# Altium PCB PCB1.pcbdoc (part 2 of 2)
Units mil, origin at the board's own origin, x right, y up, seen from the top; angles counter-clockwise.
Board outline 9373 x 7411 mil, 2 copper layers (Top Layer, Bottom Layer); 228 components, 128 nets, 653 pads, 371 vias.
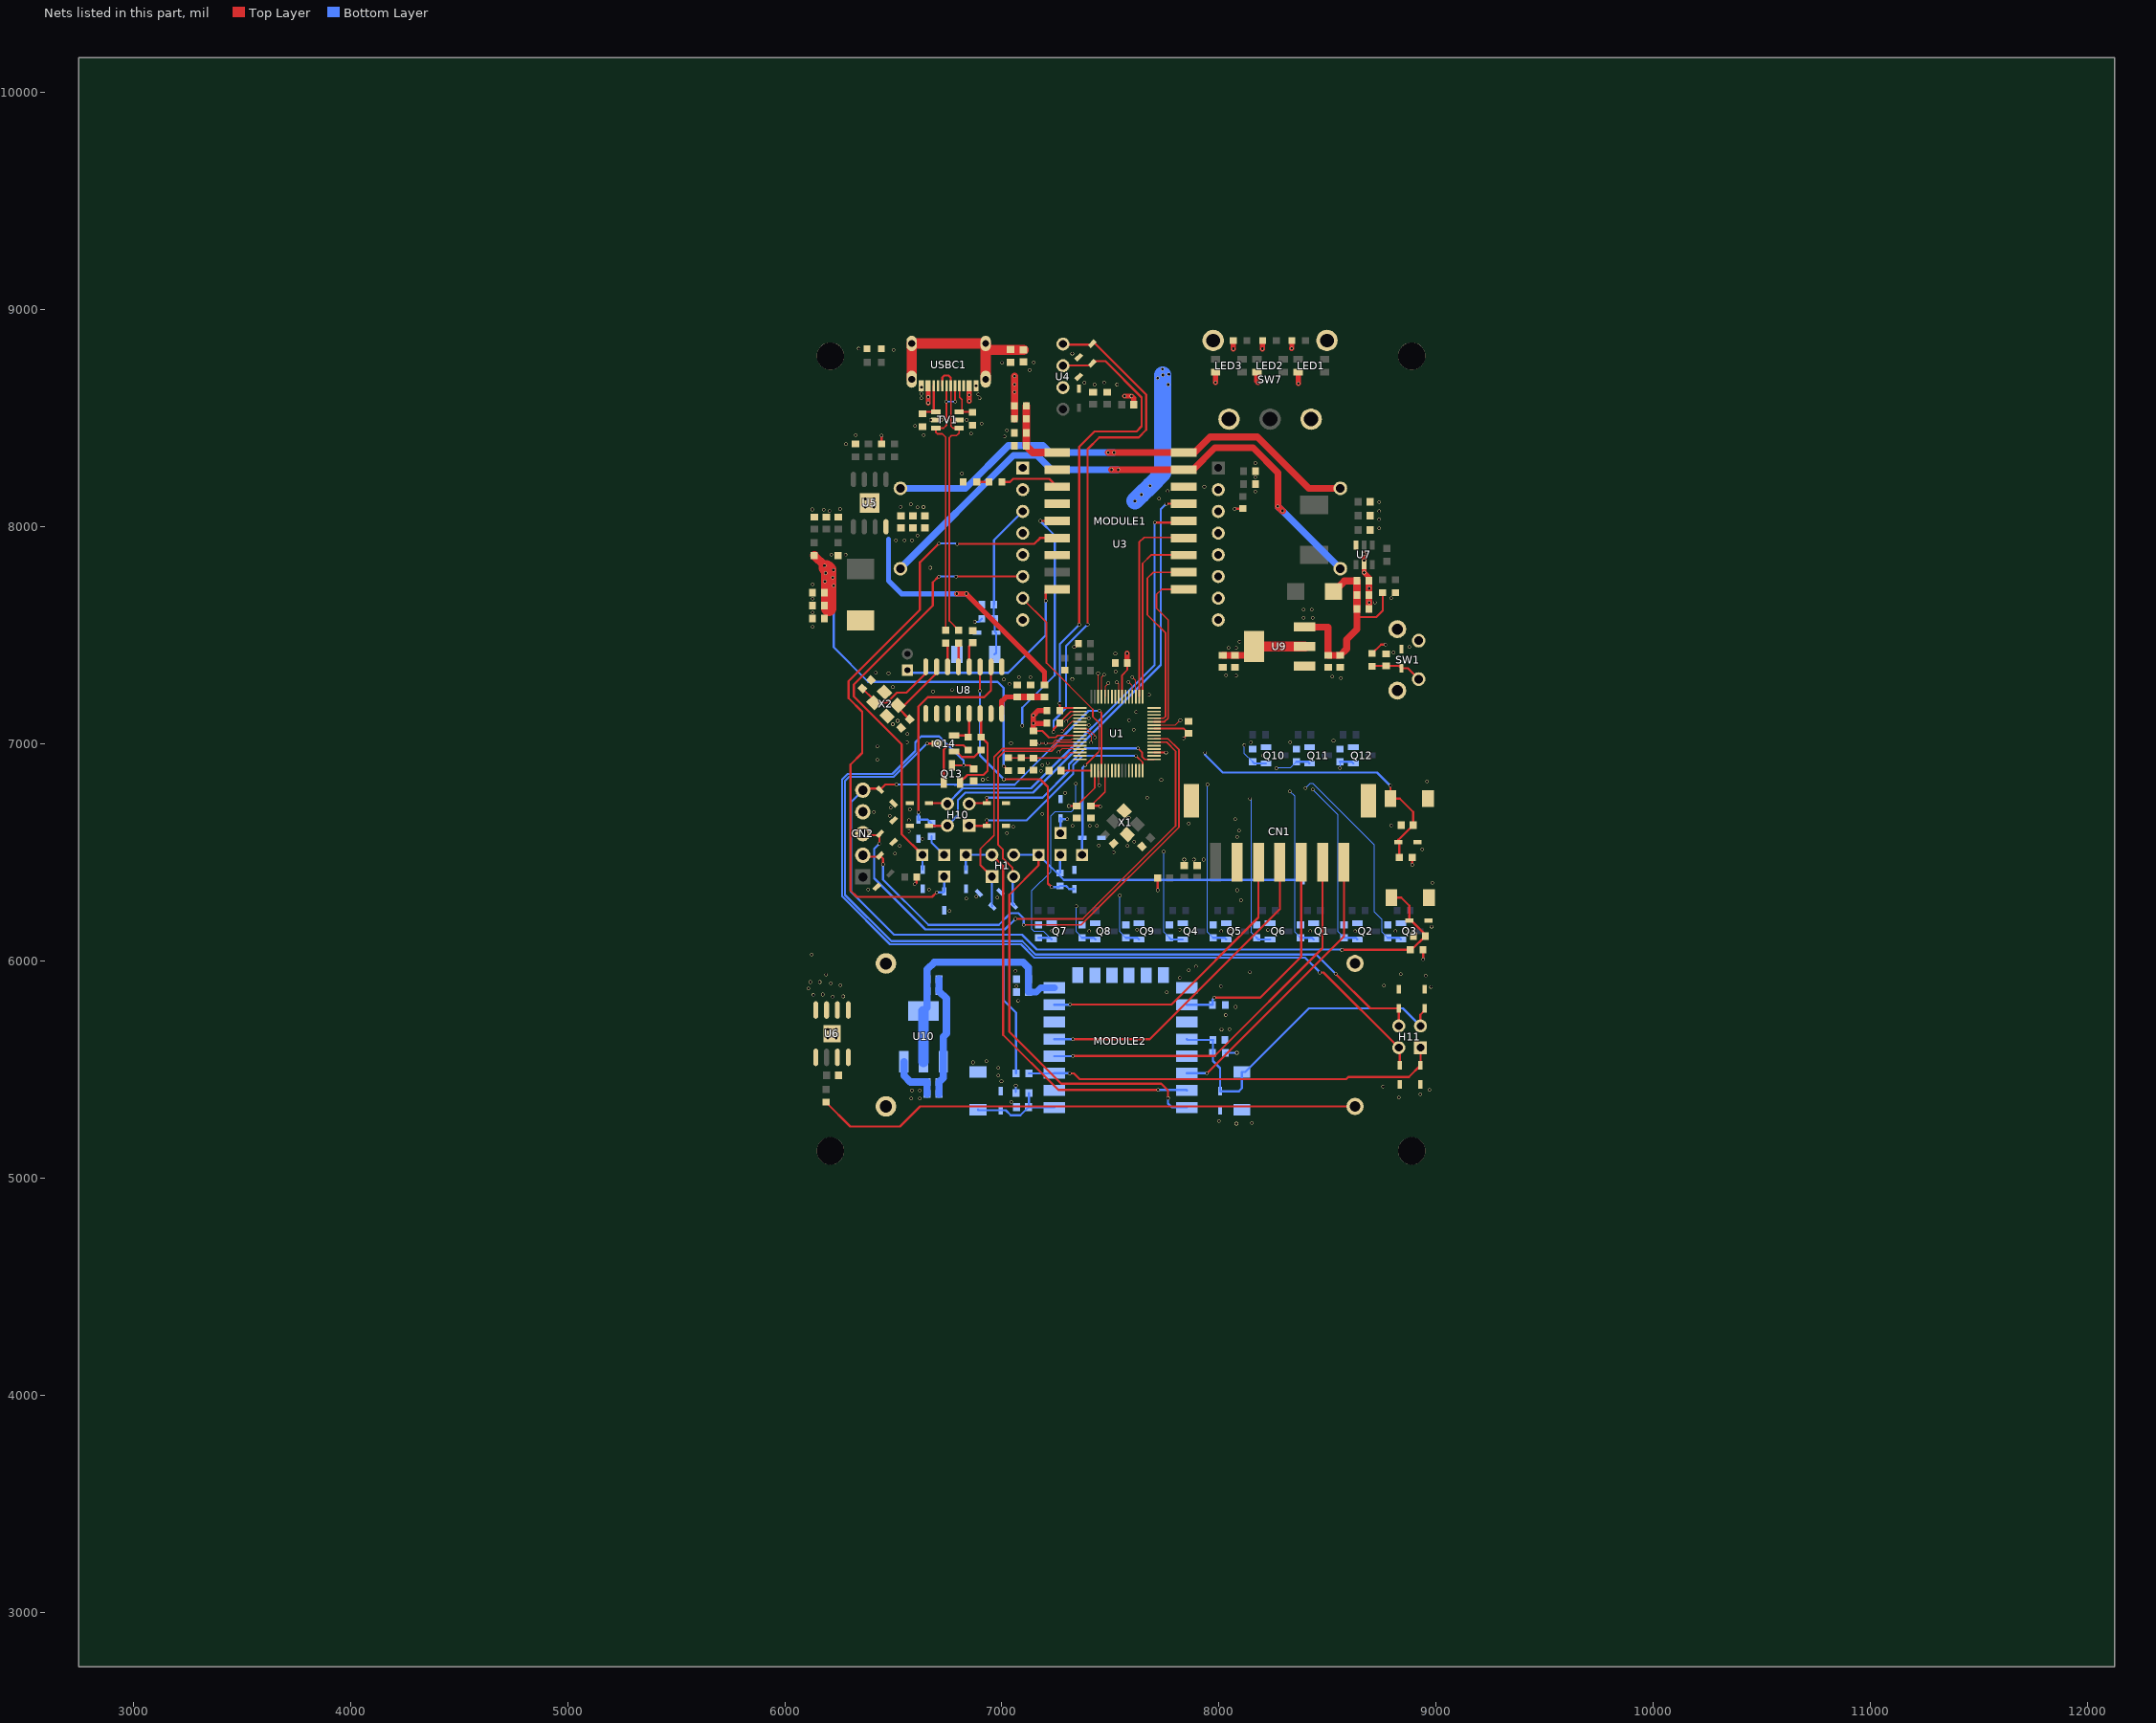
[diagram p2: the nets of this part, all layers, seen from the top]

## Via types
v1: diameter 15.75, hole 11.81, Top Layer to Bottom Layer, 371 vias

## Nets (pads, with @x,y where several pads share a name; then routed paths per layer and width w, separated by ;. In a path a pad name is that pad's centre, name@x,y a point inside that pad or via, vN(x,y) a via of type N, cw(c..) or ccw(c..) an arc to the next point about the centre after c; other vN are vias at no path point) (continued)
$5N266: MIC1.1 MODULE1.9 | length 973.1
  Top Layer w10: v1(7202,7660) 7202,7702.99 7212.04,7713.03 MODULE1.9@7255.04,7713.03
  Bottom Layer w10: MIC1.1@6565,7340.6 6577.6,7328 7029,7328 7202,7501 v1(7202,7660)
$5N267: MODULE1.3 R19.2 | length 276.3
  Top Layer w10: R19.2@6999.7,8208 7038,8208 7052,8222 7218.52,8222 MODULE1.3@7255.04,8185.48
$5N268: LED4.2 R19.1 | length 55.9
  Top Layer w10: LED4.2@6884.5,8207.8 6884.7,8208 R19.1@6940.3,8208
$5N526: C53.2 C54.2 L8.2 L9.2 MODULE1.1 | length 340.1
  Top Layer w34: L8.2@7113.18,8557.9 7112.56,8557.28 C54.2@7112.56,8433 C53.2@7112.56,8373 7142.59,8342.97 MODULE1.1@7255.04,8342.97
$6N1307: C55.1 C56.1 L10.1 U8.16 | length 261.9
  Top Layer w24: U8.16@6999.87,7140.61 6999.87,7198 7019.12,7217.26 C55.1@7071.46,7217.26
  Top Layer w32: C55.1@7071.46,7217.26 C56.1@7131.46,7217.26 L10.1@7196.46,7217.26
$6N1422: C57.1 U8.4 | length 118.1
  Top Layer w10: U8.4@6849.87,7356.02 6849.87,7450.66 C57.1@6866.46,7467.26
$6N1638: C59.1 U8.8 X2.3 | length 412.4
  Top Layer w10: C59.1@6358.11,7256.16 6410.64,7203.63 X2.3@6410.64,7190.86 6470.86,7190.86 6517,7237 6561,7237 6649.87,7325.87 U8.8@6649.87,7356.02
$6N1644: C58.2 U8.7 X2.1 | length 356.8
  Top Layer w10: C58.2@6575.11,7114.08 6520.61,7168.58 X2.1@6520.61,7178.33 6551.33,7178.33 6699.87,7326.87 U8.7@6699.87,7356.02
$6N1700: R60.2 U8.5 | length 109.8
  Top Layer w10: U8.5@6799.87,7356.02 6801.46,7357.61 R60.2@6801.46,7465.16
$6N1728: R61.2 U8.6 | length 112.6
  Top Layer w10: R61.2@6741.46,7465.16 6749.87,7456.75 U8.6@6749.87,7356.02
$6N1913: Q13.1 R62.1 | length 280.8
  Top Layer w10: Q13.1@6732.6,6823.6 6733,6824.03 6733,6975 6753,6995 6823.34,6995 R62.1@6845,6973.3
$6N1915: Q14.1 R63.1 | length 149.2
  Top Layer w10: Q14.1@6779.4,6965.6 6791.37,6965.6 6815.97,6941 6872.66,6941 R63.1@6905,6973.3
$7N380: H2.1 R64.2 | length 84.2
  Bottom Layer w10: R64.2@7268.48,6406.01 7268.48,6489.16 H2.1@7269.25,6489.93
$7N857: H6.1 R65.2 | length 110
  Bottom Layer w10: R65.2@6676.51,6574.97 6676.51,6545.97 6732.55,6489.93 H6.1@6734.25,6489.93
BAT_SENSE: C32.2 R44.2 R45.1 U1.14 | length 340.7
  Top Layer w7: R45.1@7030,6937.7 7031.7,6936 7288,6936 7313.39,6961.39 U1.14@7359.53,6961.39
BGND: BT1.2 BT2.2 C45.2 U6.5 U6.7 U6.8 U6.9
  other v1: 6198.14,5646.68 6237.51,5646.68 6198.14,5686.05 6237.51,5686.05
CAM_UART0_RX: D20.1 H8.1 U3.14 | length 2030.6
  Top Layer w10: H8.1@6634.25,6489.93 6539,6585.18 6539,6999 6318,7220 6318,7274 6682,7638 6682,7745 6709,7772 v1(6710,7772) ; v1(6789,7771.97) U3.14@7096.38,7771.97
  Bottom Layer w10: H8.1@6634.25,6489.93 6635,6489.18 D20.1@6635,6422 ; v1(6710,7772) v1(6789,7771.97)
CAM_UART0_TX: D19.1 H4.1 U3.15 | length 1360.1
  Top Layer w5: 7444,6963 7447,6966 7447,7098.21 7444,7101.21
  Top Layer w7.9: U3.15@7096.38,7671.97 7096.38,7668.73 7205.38,7559.73 7205.38,7373.5 7419,7159.88 7419,7126.21 7444,7101.21 ; v1(7384,6904) 7385,6904 7444,6963
  Bottom Layer w10: H4.1@7369.25,6489.93 7369.25,6566.25 D19.1@7371,6568 7371,6891 v1(7384,6904)
CC1: R58.2 TV1.3 USBC1.A5 | length 189.7
  Top Layer w6: USBC1.A5@6804.21,8650.59 6804.21,8597.79 6816,8586 6816,8534.25 TV1.3@6813.21,8531.46
  Top Layer w10: TV1.3@6804.21,8531.46 TV1.3@6803.15,8530.4 6862.26,8530.4 R58.2@6865,8527.7
CC2: R59.2 TV1.4 USBC1.B5 | length 190.1
  Top Layer w10: R59.2@6635,8521.7 6643.74,8530.4 TV1.4@6696.85,8530.4 6686.1,8541.15 USBC1.B5@6686.1,8650.59
CH340G_BOOT: D27.1 H11.4 Q14.3 | length 3866.8
  Top Layer w10: v1(6655,7003) Q14.3@6700.6,7003 ; v1(8537,5942) 8696.25,5782.75 D27.1@8827.59,5782.75 H11.4@8827.59,5701.75
  Bottom Layer w10: v1(6655,7003) 6501,6849 6296,6849 6278,6831 6278,6305 6491,6092 7094,6092 7155,6031 8448,6031 v1(8537,5942)
CH340G_DTR: Q14.2 R62.2 U8.13 | length 178.8
  Top Layer w10: Q14.2@6779.4,7040.4 6837.26,7040.4 R62.2@6845,7032.7 6849.87,7037.53 U8.13@6849.87,7140.61
CH340G_EN: C60.1 D26.1 H11.2 Q13.3 | length 4313.7
  Top Layer w10: Q13.3@6770,6902.4 v1(6824.17,6902.37) 6853.19,6902.37 C60.1@6870,6885.56 ; v1(8465,5948) 8481.34,5948 H11.2@8827.59,5601.75 8832.59,5596.75 D26.1@8832.59,5520.75
  Bottom Layer w10: v1(6824.17,6902.37) 6824.17,6923.83 6712,7036 6629,7036 6601,7008 6601,6968.82 6495.19,6863.02 6290.19,6863.02 6263.98,6836.81 6263.98,6299.19 6485.19,6077.98 7088.19,6077.98 7149.19,6016.98 8396.02,6016.98 v1(8465,5948)
CH340G_RTS: Q13.2 R63.2 U8.14 | length 426.5
  Top Layer w10: Q13.2@6807.4,6823.6 6841.77,6858 6915,6858 6934,6877 6934,7003.66 R63.2@6905,7032.7 6905,7135.48 U8.14@6899.87,7140.61
CH340G_RX: D15.1 R64.1 U8.3 | length 1363.1
  Top Layer w10: v1(6899,7245) 6899,7355.15 U8.3@6899.87,7356.02 ; v1(7009,6838) 7177,6838 7212,6803 7212,6358 v1(7229,6341)
  Bottom Layer w10: v1(6899,7245) 6899,6948 v1(7009,6838) ; v1(7229,6341) 7262.79,6341 R64.1@7268.48,6346.65 7295.08,6346.69 7309.38,6332.39 D15.1@7333.38,6332.39
CH340G_TX: D16.1 R65.1 U8.2 | length 1063.9
  Top Layer w10: v1(6616,6686) 6616,7173 6659,7216 6919,7216 6949.87,7246.87 U8.2@6949.87,7356.02
  Bottom Layer w10: v1(6616,6686) 6616,6653 D16.1@6615,6652 6658.8,6652 R65.1@6676.51,6634.33
D0_LCD_DC: CN1.2 MODULE2.4 | length 1837.3
  Top Layer w10: v1(7327,5564) 7980,5564 8476.84,6060.85 CN1.2@8476.84,6456.27
  Bottom Layer w10: MODULE2.4@7241.26,5562.69 7325.69,5562.69 v1(7327,5564)
D1_LCD_RST: CN1.1 MODULE2.20 | length 1326.8
  Top Layer w10: v1(7945,5484) 8575.27,6114.27 CN1.1@8575.27,6456.27
  Bottom Layer w10: MODULE2.20@7851.49,5483.94 v1@7944.94,5483.94
D5_LCD_SCK: CN1.4 MODULE2.5 | length 1503.3
  Top Layer w10: v1(7327,5641) 7681,5641 8280,6239.99 CN1.4@8280,6456.27
  Bottom Layer w10: MODULE2.5@7241.26,5641.43 7326.57,5641.43 v1(7327,5641)
D7_LCD_DIN: CN1.5 MODULE2.7 | length 1361.8
  Top Layer w10: v1(7314,5801) 7781,5801 8181.57,6201.57 CN1.5@8181.57,6456.27
  Bottom Layer w10: MODULE2.7@7241.26,5798.91 7311.91,5798.91 v1(7314,5801)
D8_LCD_CS: CN1.3 MODULE2.16 R32.2 | length 1070.7
  Top Layer w10: v1(7978,5833) 8190,5833 8378.42,6021.43 CN1.3@8378.42,6456.27
  Bottom Layer w10: MODULE2.16@7851.49,5798.9 7969.4,5798.9 R32.2@7970.3,5798 7970.3,5825.3 v1(7978,5833)
ESP32CAM_IO0_BOOT: C33.2 D9.1 R46.1 SW6.1 U3.11 | length 721.6
  Bottom Layer w10: SW6.1@6966.62,7413 6973.81,7420.19 D9.1@6973.81,7513 6967.4,7519.41 R46.1@6967.4,7578 6963.03,7582.36 C33.2@6963.03,7643 6964,7643.97 6964,7939.59 U3.11@7096.38,8071.97
ESP8266_EN: D25.1 H11.1 MODULE2.3 R31.1 | length 1921.9
  Top Layer w10: v1(7312,5483) 7332,5483 7358,5457 8585,5457 8595,5467 8873.84,5467 D25.1@8927.59,5520.75 H11.1@8927.59,5601.75
  Bottom Layer w10: R31.1@7124.7,5483 7240.31,5483 MODULE2.3@7241.26,5483.95 7311.05,5483.95 v1(7312,5483)
ESP8266_IO0_BOOT: C25.2 D7.1 D28.1 H11.3 MODULE2.18 R29.1 SW4.1 | length 1621.2
  Top Layer w10: H11.3@8927.59,5701.75 8926.59,5702.75 8926.59,5753.75 8947.59,5774.75 D28.1@8947.59,5782.75
  Bottom Layer w10: MODULE2.18@7851.49,5641.42 7854.92,5638 C25.2@7972.44,5638 7972,5637.56 7972,5541 8005,5508 D7.1@8005,5402 8006,5401 8091.38,5401 8105,5414.62 SW4.1@8105,5489.62 8120.62,5489.62 8414,5783 8846.34,5783 H11.3@8927.59,5701.75
ESP8266_RST: C26.2 D8.1 MODULE2.1 R30.1 SW5.1 | length 442.4
  Bottom Layer w10: SW5.1@6890,5316.38 6892.38,5314 D8.1@6995,5314 7018,5314 7041,5291 7085.56,5291 C26.2@7122.56,5328 C26.2@7124.7,5330.14 ; R30.1@7124.7,5393 C26.2@7124.7,5330.14 ; MODULE2.1@7241.26,5326.47 7128.37,5326.47 C26.2@7124.7,5330.14
ESP8266_UART0_RX: D13.1 H1.2 H7.1 MODULE2.21 | length 1990.1
  Top Layer w10: H1.2@6954.25,6489.93 7006,6438.18 7006,5661 7260,5407 v1(7719,5407)
  Bottom Layer w10: D13.1@6835,6422 6834.25,6422.75 H7.1@6834.25,6489.93 H1.2@6954.25,6489.93 ; v1(7719,5407) 7849.7,5407 MODULE2.21@7851.49,5405.2
ESP8266_UART0_TX: D14.1 H1.4 H3.1 MODULE2.22 | length 3246.8
  Top Layer w10: H3.1@7169.25,6489.93 7169.25,6441.25 7034,6306 7034,5675 7273,5436 7734,5436 7765,5405 v1(7765,5369)
  Bottom Layer w10: H1.4@7054.25,6489.93 H3.1@7169.25,6489.93 7285.18,6374 D14.1@8385,6374 ; v1(7765,5369) 7765,5344.96 7783.49,5326.46 MODULE2.22@7851.49,5326.46
GND: C11.1 C12.2 C13.1 C14.1 C17.1 C18.1 C19.1 C20.1 C21.1 C22.1 C25.1 C26.1 C27.1 C28.1 C29.1 C30.1 C31.2 C32.1 C33.1 C34.2 C35.2 C36.2 C37.2 C38.2 C39.2 C40.2 C41.2 C42.2 C43.2 C44.2 C46.2 C47.2 C48.2 C49.2 C50.2 C51.2 C52.1 C53.1 C54.1 C55.2 C56.2 C57.2 C58.1 C59.2 C60.2 C61.2 C62.1 C63.1 C64.1 C65.1 C66.1 C67.1 C68.1 C69.1 C70.1 CN1.6 CN2.4 D1.2 D2.2 D3.2 D4.2 D5.2 D6.2 D7.2 D8.2 D9.2 D11.2 D12.2 D13.2 D14.2 D15.2 D16.2 D17.2 D18.2 D19.2 D20.2 D21.2 D22.2 D23.2 D24.2 D25.2 D26.2 D27.2 D28.2 D29.2 D30.2 D31.2 D32.2 L1.2 LED4.1 LED8.1 LED9.1 MODULE1.2 MODULE1.16 MODULE2.15 Q1.2 Q2.2 Q3.2 Q4.2 Q5.2 Q6.2 Q7.2 Q8.2 Q9.2 Q10.2 Q11.2 Q12.2 R4.1 R5.1 R6.1 R10.1 R11.1 R12.1 R16.1 R17.1 R18.1 R26.1 R27.1 R28.1 R32.1 R44.1 R47.2 R48.2 R56.1 R57.1 R58.1 R59.1 SW1.1 SW2.2 SW3.2 SW4.2 SW5.2 SW6.2 TV1.2 U1.10 U1.19 U1.43 U1.56 U3.7 U3.12 U3.16 U4.2 U5.9 U6.1 U6.2 U6.3 U6.4 U7.2 U8.1 U9.1 U10.1 USBC1.A1 USBC1.A12 USBC1.B1 USBC1.B12 X1.2 X1.4 X2.2 X2.4 | length 1313.8
  Top Layer w5: C11.1@7145,7005.44 v1(7173.32,7005.44) v1(7201.4,7005.44) 7235.43,7005.44 7249.07,7019.08 7318.23,7019.08 7323.53,7024.38 U1.10@7359.53,7024.38 ; U1.19@7443.39,6877.53 7443.39,6816.61 v1(7449,6811) ; v1(7529,7285) 7537.87,7276.13 U1.56@7537.87,7218.47 ; U1.43@7700.47,7087.37 7799.37,7087.37 v1(7822,7110)
  Top Layer w24: v1(8668,7876) v1(8668,7846) U7.2@8668,7826.65 v1(8668,7790) 8690.56,7767.44 C50.2@8690.56,7751.89
  Top Layer w32: C51.2@8690.56,7621.89 v1(8690.56,7652.26) C49.2@8690.56,7686.89 v1(8690.56,7717.73) C50.2@8690.56,7751.89
  Bottom Layer w34: C67.1@6710.8,5388.22 C68.1@6710.8,5443.85 6730.18,5463.22 U10.1@6730.18,5536.88 6730.18,5652.18 6745,5667 6745,5827.6 C69.1@6710.8,5861.79 C70.1@6710.8,5917.9
  other v1: 8080,5252 8152,5255 8000,5264 7043.24,5352.15 8827.6,5372.63 8927,5388 8969,5407 8756,5423 6998,5447 6984,5474.06 6984,5509 6867,5534 6929,5539 8011.64,5685.62 8048,5687 8031,5752 8077.1,5789.71 7075,5818 6221,5836 6269,5838 6132,5845 6175,5847 7758.9,5857.13 6109,5874 8976.18,5881.91 8009,5885 7067.61,5885.72 8760,5887 6256,5890 6213,5899 6118.4,5904 6161,5904 7819.58,5922.84 8951,5933 6191,5939 8837,5941 8142,5950 7063,5955 7860,5958 7893,5975 6125,6031 7402.33,6138 7446.28,6138 8010.29,6138 8053.32,6138 8419.57,6138 8626.49,6138 8811.9,6138 7231,6141 7255,6141 8870.26,6140.74 8225,6144 7622,6145 7818.01,6145 8978.75,6159.41 6759,6231 8101,6281 6836,6288 6979.69,6292.87 6882,6298 8083.15,6327.2 6385,6331 6664.43,6331 8982,6361 7839.81,6468.13 7884.06,6468.14 7928.56,6468.14 6508,6495 7514,6503 8936,6516 6530.44,6531.45 7579,6531 7446,6533 7609,6551 6634.25,6564.42 8083.15,6572.35 7024,6590 6571,6599 8091.53,6600.97 7052,6619 7325.87,6623 7404.31,6623 7437,6623 8793.34,6626.26 7861,6635 6572,6649 8075,6654 7584,6661 6483,6670 7186,6678 6411,6688 6576.18,6699.41 6488,6707 7669,6753 7291,6775 8958,6829 7734,6835 6912,6836 6936,6840 7180.37,6877.47 7186,6903 7211,6913 6426,6927.94 8202.08,6948 6426,6990 7042,7005 6562,7009 8146.23,7009 8328,7009 8527,7015 6564.64,7046.85 7607,7067 6498,7091.63 6520,7107 7586,7110 7619,7148 7677,7227 6683,7243 6770,7250 6498,7262 7035,7277 7009,7297 7324,7299 8561,7304 7078,7309 7131.09,7309 8521,7311 8077.88,7315.98 8033,7317 6478,7326 6418.81,7329.08 7523,7334 7522.44,7416.6 8804,7422 8876,7448 6128.9,7539.38 6128.9,7606.26 8717.72,7653.18 6128.9,7670.37 8792.67,7672.36 6128.9,7735.78 6670,7812 6280,7872 6214.68,7872.89 8737,7993.85 8737,8034.83 8737,8072.38 6206.78,8073.2 6179,8080 6127,8081 6254,8083 6371.77,8090.38 6411.14,8090.38 6612,8091 6639,8092 6533.42,8093.37 6581,8105 8737,8115 6371.77,8129.75 6411.14,8129.75 7724,8131 8166.78,8163.17 7763,8165 7932.37,8185.48 8166.78,8230.05 6816,8246 8167.56,8294.71 6282,8381 7011.66,8417.47 6327,8424 6640,8424 6858,8430 7023,8445 6601,8465 6906,8477 6838.86,8493 6629,8593.85 6897,8594 6892,8611 6629,8614 6630,8644 6880.98,8650.59 7427,8656 7531,8656 7380.13,8664.69 7470,8665 7128,8723 7001,8757 7147,8759 7324,8799 6500.54,8815.6 6341.22,8821.5
HT32_LDO: C12.1 U1.17 | length 139.5
  Top Layer w7: C12.1@7272.56,6878 7411.42,6878 U1.17@7411.89,6877.53
KEY0_USER: C21.2 D1.1 R22.1 SW1.2 | length 240.4
  Top Layer w10: R22.1@8705,7358.3 8707.14,7360.44 C21.2@8770,7360.44 8828.56,7360.44 D1.1@8840,7349 8869.63,7349 SW1.2@8919.21,7299.42
NRST: C20.2 CN2.5 D2.1 D32.1 R21.1 SW3.1 U1.20 | length 5071.3
  Top Layer w7.9: v1(7448,7154) 7459.13,7142.87 U1.20@7459.13,6877.53
  Top Layer w10: CN2.5@6360,6788 6367,6795 6433,6795 D32.1@6438.89,6789.11 6463.77,6814 v1(6514,6814) ; v1@8568,6053 R21.1@8880.3,6053 8886.43,6053 C20.2@8949.58,6116.15 8949.58,6122.15 8883.73,6188 D2.1@8876,6188 8876,6256 8839,6293 SW3.1@8793.38,6293
  Bottom Layer w10: CN2.5@6360,6788 6305,6733 6305,6321 6503.34,6122.66 7092.45,6122.66 7161.45,6053.66 8564.47,6053.66 v1(8566.47,6051.66) ; v1(6514,6814) 6781,6814 6782,6813 7059,6813 7399,7153 v1@7450,7153
PA0_IR_SCL: D6.1 R67.1 U1.1 U4.3 | length 2249.5
  Top Layer w7.9: R67.1@7266.7,7155 7277.77,7166.11 U1.1@7359.53,7166.11
  Top Layer w10: R67.1@7266.7,7155 v1(7266.66,7188) ; U4.3@7281.42,8742.7 7282.83,8744.11 7406.11,8744.11 D6.1@7416.11,8754.11 7426.11,8764.11 7476.89,8764.11 7644,8597 7644,8464 7620,8440 7427,8440 7356,8369 v1(7356,7550)
  Bottom Layer w10: v1(7266.66,7188) 7266.66,7460.66 v1(7356,7550)
PA1_IR_SDA: D5.1 R66.1 U1.2 U4.4 | length 2498.6
  Top Layer w7.9: R66.1@7266.7,7097 7266.66,7100 7317.02,7150.36 U1.2@7359.53,7150.36
  Top Layer w10: v1(7238,7055) 7238,7070 7265,7097 R66.1@7266.7,7097 ; U4.4@7281.42,8842.7 7284.42,8839.7 7411.7,8839.7 D5.1@7416.11,8844.11 7423.18,8851.18 7665,8609.37 7665,8448 7630,8413 7449,8413 7395,8359 v1(7395,7551)
  Bottom Layer w10: v1(7238,7055) 7238,7107 7296,7165 7296,7452 v1(7395,7551)
PA2_RGB1_B: Q1.1 R4.2 U1.3 | length 2409.1
  Top Layer w5: v1(7297,7103) 7297,7106 7325.61,7134.61 U1.3@7359.53,7134.61
  Inner2 w5: v1(7297,7103) 7297,7039 7271,7013 7220,7013 7186,7047 7186,7066 7301,7181 7873,7181 8258,6796 8315,6796 8326,6785 v1(8326,6782)
  Bottom Layer w5: v1(8326,6782) 8349,6759 8349,6134.08 R4.2@8374.78,6108.3
  Bottom Layer w10: R4.2@8374.78,6108.3 8428.22,6108.3 Q1.1@8435.92,6100.6
PA3_RGB2_R: Q6.1 R12.2 U1.4 | length 1655.1
  Top Layer w5: U1.4@7359.53,7118.87 7359.66,7119 v1(7400,7119)
  Inner2 w5: v1(7400,7119) 7769,6750 v1(8143,6750)
  Bottom Layer w5: v1(8143,6750) 8148,6745 8148,6133.99 R12.2@8173.69,6108.3
  Bottom Layer w10: R12.2@8173.69,6108.3 8181.39,6100.6 Q6.1@8234.84,6100.6
PA4_RGB2_G: Q5.1 R11.2 U1.5 | length 1784.4
  Top Layer w5: v1(7276,7060) 7280.41,7060 7323.53,7103.12 U1.5@7359.53,7103.12
  Inner2 w5: v1(7276,7060) 7276,7135 7305,7164 7400,7164 7552,7012 7670,7012 7868,6814 v1(7946,6814)
  Bottom Layer w5: v1(7946,6814) 7946,6134.91 R11.2@7972.61,6108.3
  Bottom Layer w10: R11.2@7972.61,6108.3 8026.05,6108.3 Q5.1@8033.75,6100.6
PA5_RGB2_B: Q4.1 R10.2 U1.6 | length 1238.7
  Top Layer w5: U1.6@7359.53,7087.37 7360.16,7088 v1(7400,7088)
  Inner2 w5: v1(7400,7088) 7745,6743 v1(7745,6504)
  Bottom Layer w5: v1(7745,6504) 7745,6134.82 R10.2@7771.52,6108.3
  Bottom Layer w10: R10.2@7771.52,6108.3 7779.22,6100.6 Q4.1@7832.66,6100.6
PA6_RGB3_R: Q9.1 R18.2 U1.7 | length 1136.1
  Top Layer w5: U1.7@7359.53,7071.62 7395.52,7071.62 7428,7039.14 v1(7428,7031)
  Inner2 w5: v1(7428,7031) 7543,6916 v1(7543,6303)
  Bottom Layer w5: v1(7543,6303) 7543,6135.73 R18.2@7570.43,6108.3
  Bottom Layer w10: R18.2@7570.43,6108.3 7623.88,6108.3 Q9.1@7631.58,6100.6
PA7_RGB3_G: Q8.1 R17.2 U1.8 | length 1149.7
  Top Layer w5: U1.8@7359.53,7055.87 7395.52,7055.87 7411,7040.39 v1(7411,7006)
  Inner2 w5: v1(7342,6254) 7342,6336 7478,6472 7478,6886 7411,6953 v1(7411,7006)
  Bottom Layer w5: v1(7342,6254) 7342,6135.65 R17.2@7369.35,6108.3
  Bottom Layer w10: R17.2@7369.35,6108.3 7422.79,6108.3 Q8.1@7430.49,6100.6
PA9_BOOT: C19.2 D3.1 R20.1 SW2.1 U1.35 | length 1586.9
  Top Layer w7.9: U1.35@7700.47,6961.39 v1(7756,6961.39)
  Top Layer w10: v1(8788.97,6808) SW2.1@8788.97,6749.25 8831.75,6749.25 8893.82,6687.19 C19.2@8893.82,6626.15 8893.15,6626.15 8826,6559 D3.1@8826,6548 8830.3,6543.7 R20.1@8830.3,6478
  Inner2 w10: v1(7756,6961.39) v1(7935,6961.39)
  Bottom Layer w10: v1(7935,6961.39) 7935,6951 8017,6869 8727.97,6869 v1(8788.97,6808)
PA12_SWCLK: CN2.3 D30.1 U1.38 | length 2440.3
  Top Layer w7.9: v1(7063,6195) 7372,6195 7800,6623 7800,6967 7758.37,7008.63 U1.38@7700.47,7008.63
  Top Layer w10: CN2.3@6360,6588 6367,6581 6433,6581 D30.1@6436,6584 ; v1(6436,6541.65) D30.1@6436,6584 ; D30.1@6438.89,6586.89 D30.1@6436,6584
  Bottom Layer w10: v1(6436,6541.65) 6412,6517.65 6412,6382 6648,6146 7014,6146 v1(7063,6195)
PA13_SWDIO: CN2.2 D31.1 U1.39 | length 2390.5
  Top Layer w7.9: v1(7100,6167) 7365,6167 7816,6618 7816,6973 7764.62,7024.38 U1.39@7700.47,7024.38
  Top Layer w10: CN2.2@6360,6488 6367,6481 6433,6481 D31.1@6438.89,6486.89 6453,6472.77 v1(6453,6446)
  Bottom Layer w10: v1(6453,6446) 6453,6376 6662,6167 6986,6167 7040,6221 7076,6221 7100,6197 v1@7100,6168
PB0_SPEECH: MODULE1.10 U1.44 | length 799.6
  Top Layer w7.9: U1.44@7700.47,7103.12 7749.12,7103.12 7766,7120 7766,7572 7712,7626 7712,7689 7736.04,7713.04 MODULE1.10@7837.72,7713.04
PB1_SPEECH: MODULE1.11 U1.45 | length 907.3
  Top Layer w7.9: U1.45@7700.47,7118.87 7744.87,7118.87 7754,7128 7754,7512 7670,7596 7670,7764 7697,7791 7836.94,7791 MODULE1.11@7837.72,7791.78
PB2_SPEECH: MODULE1.12 U1.49 | length 819.6
  Top Layer w7.9: U1.49@7648.11,7218.47 7648.11,7832.11 7687,7871 7837.24,7871 MODULE1.12@7837.72,7870.52
PB3_SPEECH: MODULE1.13 U1.50 | length 926.8
  Top Layer w7.9: U1.50@7632.36,7218.47 7632.36,7929.36 7655,7952 7834.98,7952 MODULE1.13@7837.72,7949.26
PB4_LED1: Q10.1 R26.2 U1.51 | length 899.8
  Top Layer w5: v1(7601,7309) 7616.61,7293.39 U1.51@7616.61,7218.47
  Inner2 w5: v1(7601,7309) 7802,7309 8116,6995 v1(8117,6995)
  Bottom Layer w5: v1(8117,6995) 8117,6956.3 R26.2@8155,6918.3
  Bottom Layer w10: R26.2@8155,6918.3 8162.7,6910.6 Q10.1@8216.14,6910.6
PB5_LED2: Q11.1 R27.2 U1.52 | length 1091.3
  Top Layer w5: v1(7583,7287) 7600.87,7269.13 U1.52@7600.87,7218.47
  Inner2 w5: v1(7583,7287) 7798,7287 8196,6889 v1@8265,6889
  Bottom Layer w5: v1(8264,6889) 8326.79,6889 R27.2@8356.09,6918.3
  Bottom Layer w10: R27.2@8356.09,6918.3 8409.53,6918.3 Q11.1@8417.23,6910.6
PB6_LED3: Q12.1 R28.2 U1.60 | length 1503.2
  Top Layer w5: U1.60@7474.88,7218.47 7475,7218.59 7475,7265 v1(7491,7281)
  Inner2 w5: v1(7491,7281) 7499,7281 7572,7208 7849,7208 7867,7190 7876.73,7190 8239.86,6826.86 8319.86,6826.86 ; 8321,6828 8319.86,6826.86 ; v1(8557,6890) 8557,6876 8446,6765 8381.73,6765 8319.86,6826.86
  Bottom Layer w5: v1(8557,6890) 8557.17,6890.17 R28.2@8557.17,6918.3
  Bottom Layer w10: R28.2@8557.17,6918.3 8610.62,6918.3 Q12.1@8618.32,6910.6
PB7_RGB1_R: Q3.1 R6.2 U1.61 | length 2247.9
  Top Layer w5: U1.61@7459.13,7218.47 7459.13,7309.13 v1(7470,7320)
  Inner2 w5: v1(7470,7320) 7514,7364 7831,7364 v1(8398,6797)
  Bottom Layer w5: v1(8398,6797) 8419,6818 8434,6818 8716,6536 8716,6226 8750,6192 8750,6135.25 R6.2@8776.95,6108.3
  Bottom Layer w10: R6.2@8776.95,6108.3 8830.39,6108.3 Q3.1@8838.09,6100.6
PB8_RGB1_G: Q2.1 R5.2 U1.62 | length 2174.9
  Top Layer w5: v1(7443,7327) 7443,7218.86 U1.62@7443.39,7218.47
  Inner2 w5: v1(7443,7327) 7502.35,7386.35 7825.65,7386.35 8398,6814 8408,6814 v1(8431,6791)
  Bottom Layer w5: v1(8431,6791) 8548,6674 8548,6136.16 R5.2@8575.86,6108.3
  Bottom Layer w10: R5.2@8575.86,6108.3 8629.31,6108.3 Q2.1@8637.01,6100.6
PC4_UART0_TX: D11.1 H1.1 U1.11 | length 1161.6
  Top Layer w7.9: 6901,6517 6964,6580 6964,6941 7002,6979 7223.77,6979 7253.4,7008.63 U1.11@7359.53,7008.63
  Top Layer w10: 6901,6517 6901,6443.18 H1.1@6954.25,6389.93
  Bottom Layer w10: H1.1@6954.25,6389.93 6954.25,6253.75 D11.1@6956.11,6251.89
PC5_UART0_RX: D12.1 H1.3 U1.12 | length 1114.1
  Top Layer w7.9: H1.3@7054.25,6389.93 7049,6395.18 7049,6429 7005,6473 7005,6513 6983,6535 6983,6938 7012,6967 7229,6967 7254.88,6992.88 U1.12@7359.53,6992.88
  Bottom Layer w10: H1.3@7054.25,6389.93 7050.11,6385.79 7050.11,6262.89 D12.1@7056.11,6256.89
PC6_RGB3_B: Q7.1 R16.2 U1.13 | length 1242.4
  Top Layer w5: v1(7262,6962) 7277.13,6977.13 U1.13@7359.53,6977.13
  Inner2 w5: v1(7262,6962) 7262,6897 v1(7341,6818)
  Bottom Layer w5: Q7.1@7221.7,6108.3 7194,6136 7150,6136 7138,6148 7138,6325 7225,6412 7225,6669 7246,6690 7320,6690 7341,6711 v1(7341,6818)
  Bottom Layer w10: R16.2@7168.26,6108.3 7221.7,6108.3 Q7.1@7229.4,6100.6
PC12_UART1_TX: D21.1 H10.1 U1.32 | length 1022.6
  Top Layer w7.9: v1(7618,6946) 7648.11,6915.89 U1.32@7648.11,6877.53
  Top Layer w10: H10.1@6849.12,6625.13 6851.25,6623 D21.1@6931,6623 v1(6931,6649)
  Bottom Layer w10: v1(6931,6649) 7114,6649 7329,6864 7329,6903 7372,6946 v1(7618,6946)
PC13_UART1_RX: D22.1 H10.3 U1.33 | length 1023.8
  Top Layer w7.9: v1(7627,6980) 7646,6961 7646,6941 7657.11,6929.89 U1.33@7700.47,6929.89
  Top Layer w10: H10.3@6849.12,6725.13 6851.98,6728 D22.1@6931,6728 v1@6931,6755
  Bottom Layer w10: v1(6931,6754) 7187,6754 7309,6876 7309,6907 7382,6980 v1(7627,6980)
SPEECH_B0_UART0_TX: D24.1 H10.4 MODULE1.14 | length 2098.3
  Top Layer w10: D24.1@6664,6728 6746.25,6728 H10.4@6749.12,6725.13 ; v1(7704,8020) 7829.72,8020 MODULE1.14@7837.72,8028
  Bottom Layer w10: H10.4@6749.12,6725.13 6819.98,6796 7135,6796 7703,7364 7703,8019 v1(7704,8020)
SPEECH_B1_UART0_RX: D23.1 H10.2 MODULE1.15 | length 2249.5
  Top Layer w10: D23.1@6664,6623 6746.98,6623 H10.2@6749.12,6625.13 ; v1(7757,8107) 7837.46,8107 MODULE1.15@7837.72,8106.74
  Bottom Layer w10: H10.2@6749.12,6625.13 6750.13,6625.13 6798,6673 6798,6743 6831.99,6776.99 7143.99,6776.99 7732,7365 7732,8082 v1(7757,8107)
SPEECH_B6_UART1_RX: D18.1 H9.1 MODULE1.6 | length 2899.4
  Top Layer w10: v1(6700,6317) 6679,6296 6333,6296 6303,6326 6303,6905 6357,6959 6357,7149 6294,7212 6294,7290 6623,7619 6623,7837 v1(6710,7924) ; v1(6794,7922) 7148.75,7922 7176,7949.25 MODULE1.6@7255.04,7949.25
  Bottom Layer w10: v1(6700,6317) 6730,6317 D18.1@6735,6322 6735,6389.18 H9.1@6734.25,6389.93 ; v1(6710,7924) 6792,7924 v1(6794,7922)
SPEECH_B7_UART1_TX: D17.1 H5.1 MODULE1.5 | length 1730.1
  Top Layer w10: v1(7177,8028) MODULE1.5@7255.04,8028
  Inner2 w10: v1(7094,7085) 7094,6861 v1(7301,6654)
  Bottom Layer w10: v1(7094,7085) 7094,7168 7244,7318 7244,7961 v1(7177,8028) ; H5.1@7269.25,6589.93 7270,6590.68 D17.1@7270,6659 7275,6654 v1(7301,6654)
SPK+: MODULE1.18 SPK1.1 SPK2.1 | length 2276.4
  Top Layer w32: v1(7489,8343) v1(7517,8343) ; v1(7517,8343) MODULE1.18@7837.72,8342.96 ; MODULE1.18@7837.72,8342.96 7886.72,8342.96 7958.76,8415 8177,8415 8413.84,8178.16 SPK1.1@8558.6,8178.16
  Bottom Layer w32: SPK2.1@6532.69,8178.16 6832.69,8178.16 7029.53,8375 7190,8375 7222,8343 v1(7489,8343) ; v1(7489,8343) v1(7517,8343)
SPK-: MODULE1.17 SPK1.2 SPK2.2 | length 2695.2
  Top Layer w32: v1(7505,8264) v1(7536,8264) 7837.5,8264 MODULE1.17@7837.72,8264.22 7880.22,8264.22 7981,8365 8157,8365 8271,8251 v1(8271,8095.68) v1(8292.56,8074.12)
  Bottom Layer w32: SPK2.2@6532.69,7808.08 6532.69,7809.37 7053.32,8330 7162,8330 7228,8264 v1(7505,8264) v1(7536,8264) ; v1(8271,8095.68) v1(8292.56,8074.12) SPK1.2@8558.6,7808.08
USB_DN: R61.1 TV1.6 USBC1.A7 USBC1.B7 | length 1316.4
  Top Layer w8: R61.1@6741.46,7524.52 6741.46,8413.54 6726,8429 6703,8429 6696.85,8435.15 TV1.6@6696.85,8455.6 6731.51,8455.6 6744,8468.09 v1(6744,8578) ; v1@6742,8576 v1(6744,8578) ; USBC1.A7@6745.16,8650.59 6745.16,8579.16 v1(6744,8578) ; USBC1.B7@6784.53,8650.59 6784.53,8579.47 v1(6786,8578)
  Bottom Layer w8: v1(6744,8578) v1(6786,8578)
USB_DP: R60.1 TV1.1 USBC1.A6 USBC1.B6 | length 1331.7
  Top Layer w7: USBC1.A6@6764.84,8650.59 6764.84,8465.16 6774.4,8455.6 TV1.1@6803.15,8455.6
  Top Layer w8: R60.1@6801.46,7524.52 6758,7567.94 6758,8411 6768,8421 6791,8421 6803.15,8433.15 TV1.1@6803.15,8455.6
  Top Layer w10: USBC1.B6@6725.47,8650.59 6725.47,8688.47 6735,8698 6754.84,8698 6764.84,8688 USBC1.A6@6764.84,8650.59
USB_SHIELD: C52.2 R57.2 USBC1.0 USBC1.1 USBC1.2 USBC1.3 | length 844.4
  Top Layer w48: USBC1.1@6584.72,8680.84 USBC1.2@6584.73,8845.41 USBC1.3@6925.27,8845.41 USBC1.3@6925.28,8815.56 ; USBC1.0@6925.28,8680.84 USBC1.3@6925.28,8815.56 ; C52.2@7100,8815.56 USBC1.3@6925.28,8815.56
USB_VBUS: C42.1 C43.1 C44.1 L10.2 TV1.5 U5.8 USBC1.A4 USBC1.A9 USBC1.B4 USBC1.B9 | length 1285.3
  Top Layer w24: v1(6661,8571.92) v1(6661,8599) 6661,8625 ; v1(6792,7693) v1(6836,7693) 7196.46,7332.54 L10.2@7196.46,7272.37 ; v1(6850,8579.62) v1(6850,8608) 6850,8625
  Bottom Layer w24: 6478,7943 6478,7753 6538,7693 v1(6792,7693) v1(6836,7693)
  other v1: 6511.56,7939 6551.32,7939 6586,7939 6611,7961 6672.29,8493 6720.44,8493
VBAT: BT1.1 BT2.1 C39.1 C40.1 C41.1 L6.2 R45.2 R51.1 R52.1 R53.2 SW7.1 | length 4610.1
  Top Layer w10: R53.2@6190.46,5350.57 6302.02,5239 6531,5239 6623.3,5331.3 BT1.1@8626.3,5331.3 ; R51.1@6446.03,8383.18 v1(6446,8421) ; v1(7008,6898) 7010.3,6898 R45.2@7030,6878.3
  Top Layer w40: R52.1@6136.03,7868.78 v1(6183.25,7821.6)
  Top Layer w50: v1(6183.25,7821.6) 6192.25,7812.6
  Top Layer w70: 6192.25,7812.6 6202.25,7802.6 6202.25,7625
  Inner2 w10: v1(6446,8421) 6522,8421 6643,8300
  Bottom Layer w10: v1(6226,7729) 6226,7446 6385,7287 6980,7287 7008,7259 v1(7008,6898)
  other v1: 6185,7750 6222,7767 6188,7788 6225,7802
VCC_ESP8266_3.3V: C27.2 C28.2 C69.2 C70.2 MODULE2.8 R31.2 U10.2 U10.4 | length 1699.3
  Bottom Layer w10: 7008.46,5996 7008,5995.54 7008,5820 7065.3,5762.7 R31.2@7065.3,5483
  Bottom Layer w32: C27.2@7122.56,5918 C28.2@7122.56,5858 7159,5858 7178.65,5877.65 MODULE2.8@7241.26,5877.65
  Bottom Layer w34: U10.4@6639.63,5770.74 6655.68,5786.79 C69.2@6655.68,5861.79 C70.2@6655.68,5917.9 6655.68,5961.68 6690,5996 7008.46,5996 7097,5996 7122.56,5970.44 C27.2@7122.56,5918
  Bottom Layer w48: U10.2@6639.63,5536.88 U10.4@6639.63,5770.74
VCC_MCU_3.3V: C11.2 C13.2 C14.2 C17.2 C18.2 C65.2 C66.2 L2.2 L11.2 R20.2 R21.2 R22.2 R29.2 R30.2 R46.2 R66.2 R67.2 U1.9 U1.18 U1.21 U1.42 U1.55 U9.2 U9.4 | length 2051.6
  Top Layer w7.9: 7216,7031 7247.95,7031 7257.08,7040.13 U1.9@7359.53,7040.13 ; C13.2@7345,6715.56 7427.64,6798.2 U1.18@7427.64,6877.53 ; C14.2@7410,6715.56 7474.88,6780.44 U1.21@7474.88,6877.53 ; U1.55@7553.62,7218.47 7553.62,7317.62 7577.56,7341.56 C17.2@7577.56,7373 ; U1.42@7700.47,7071.62 7838.82,7071.62 C18.2@7860,7050.44
  Top Layer w10: v1(6599,6354) 6607.56,6362.56 L11.2@6607.56,6388 ; C11.2@7145,7060.56 7186.44,7060.56 7216,7031 ; v1(7308.34,6714.78) 7344.22,6714.78 C13.2@7345,6715.56 ; v1(7333,7447) 7336.44,7447 L2.2@7352.44,7463 ; C14.2@7410,6715.56 7448.44,6715.56 v1(7453,6711) ; v1(7835.62,7026.85) 7836.41,7026.85 C18.2@7860,7050.44 ; R22.2@8705,7417.7 8746.3,7459 v1(8767,7459) ; v1(8889.7,6444) R20.2@8889.7,6478 ; v1(8939.7,6008) R21.2@8939.7,6053
  Top Layer w25: C11.2@7145,7060.56 v1(7145.01,7095.69) ; R66.2@7207.3,7097 7206.03,7095.69 v1(7145.01,7095.69) ; R67.2@7207.3,7155 7167.66,7155 v1(7145.01,7132.35) v1(7145.01,7095.69) ; v1(7577,7418) 7577,7373.56 C17.2@7577.56,7373
  Top Layer w32: C66.2@8017,7408.62 C65.2@8073,7408.62 8119.49,7408.62 U9.4@8160.55,7449.68
  Top Layer w48: U9.4@8160.55,7449.68 U9.2@8394.4,7449.68
  Bottom Layer w10: v1(6875,7563) 6892.99,7563 R46.2@6907.99,7578 ; R30.2@7064,5399 v1(7064,5427) ; R29.2@8029.7,5578 v1(8082,5578)
  other v1: 8044,7443 8077.88,7443.47 8095,7472
VSYS_5V: C49.1 C50.1 C51.1 C63.2 C64.2 C67.2 C68.2 D10.1 L3.2 L4.1 L5.2 L8.1 L9.1 LED1.1 LED2.1 LED3.1 LED5.2 LED6.2 LED7.2 R55.2 U9.3 U10.3 | length 4348.1
  Top Layer w10: v1(7717,6327) 7717.44,6327.44 L4.1@7717.44,6383 ; v1@8074,8084 8108.56,8084 L5.2@8110,8085.44 ; 8635.44,7596.56 8647,7585 8724,7585 8754,7615 8754,7696.23 R55.2@8753,7697.19
  Top Layer w24: v1(7564.8,8603) v1(7597,8603) 7607.56,8592.44 L3.2@7607.56,8563 ; v1(7984,8666) LED3.1@7984,8713.5 ; v1(8065,8821) 8065.5,8821.5 LED5.2@8065.5,8858.2 ; LED2.1@8174,8713.5 8174,8671.59 v1(8179.9,8665.69) ; v1(8199.9,8821) 8200.5,8821.6 LED6.2@8200.5,8858.2 ; v1(8335,8823) 8335.5,8823.5 LED7.2@8335.5,8858.2 ; LED1.1@8364,8713.5 8365,8712.5 v1(8365,8661)
  Top Layer w32: L8.1@7058.07,8557.9 v1(7058.07,8622) v1(7058.07,8657.05) v1(7058.07,8695) ; U9.3@8394.4,7540.23 8395.63,7539 8502,7539 C63.2@8502,7408.62 C64.2@8558,7408.62 8588,7438.62 8588,7482 8635.44,7529.44 8635.44,7596.56 C51.1@8635.44,7621.89
  Top Layer w34: L9.1@7058.07,8497.9 L8.1@7058.07,8557.9 ; D10.1@8526.61,7703 8529.11,7703 8578,7751.89 C50.1@8635.44,7751.89 C49.1@8635.44,7686.89 C51.1@8635.44,7621.89
  Inner2 w10: v1(6623,5368) 6683,5308 7196,5308 7717,5829 v1(7717,6327)
  Bottom Layer w34: U10.3@6549.08,5536.88 6549.08,5473.77 6579,5443.85 C68.2@6655.68,5443.85 C67.2@6655.68,5388.22
  Bottom Layer w80: v1(7613,8120) v1(7642.18,8149.18) v1(7682.81,8189.81) 7741,8248 v1(7741,8700)
  other v1: 6582.44,5368 6585.97,5405 6622,5405 8389,7582 8431,7582 8389.46,7620 8427,7620 8072,8083 7766,8656 7717,8685 7769,8704 7739,8727
"": CN1.8 CN1.9 MODULE1.4 MODULE1.7 MODULE2.2 MODULE2.6 MODULE2.9 MODULE2.10 MODULE2.11 MODULE2.12 MODULE2.13 MODULE2.14 MODULE2.17 MODULE2.19 SW1.3 SW1.4 SW7.3 SW7.4 SW7.5 TP1.1 TP2.1 TP3.1 TP4.1 U1.15 U1.16 U1.22 U1.23 U1.24 U1.25 U1.28 U1.29 U1.30 U1.31 U1.34 U1.36 U1.37 U1.40 U1.41 U1.46 U1.47 U1.48 U1.53 U1.54 U1.57 U1.58 U1.59 U3.1 U3.2 U3.3 U3.4 U3.5 U3.6 U3.9 U3.10 U3.13 U7.6 U8.9 U8.10 U8.11 U8.12 U8.15 USBC1.A8 USBC1.B8

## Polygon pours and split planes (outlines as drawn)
VBAT on Inner2 (solid, remove dead copper, pour order 0): 6136,7714.05 6136,7826 6882.49,8572.49 8489.49,8572.49 8726.31,8335.66 8726.31,5253.08 8466,5253.08 8466,8194.18 8388.22,8271.97 6909.89,8271.97 6350,7712.08 6137.98,7712.08
USB_VBUS on Bottom Layer (solid, remove dead copper, pour order 1): 6349,8620 6870.8,8620 6880.98,8609.82 6880.98,8562.95 6646.03,8328 6646.03,7953.79 6607.49,7915.26 6200.94,7915.26 6200.94,8317.94 6349,8466
VSYS_5V on Inner2 (solid, remove dead copper, pour order 2): 7552.44,8589.37 7552.44,8749.44 7689,8886 8425.6,8886 8425.6,8669.81 8368.95,8613.16 7709.16,8613.16 7685,8589 7552.82,8589
VSYS_5V on Top Layer (solid, remove dead copper, pour order 3): 8345,7637 8638.83,7637 8653.94,7621.89 8653.94,7547.94 8588,7482 8588,7436.65 8558,7406.65 8502,7406.65 8502,7531.43 8345.31,7531.43 8345,7531.74
VSYS_5V on Inner2 (solid, remove dead copper, pour order 4): 7519,8211 8045.88,8211 8440,7816.88 8440,7547.61 8431.39,7539 8069,7539 7519,8089
VSYS_5V on Inner2 (solid, remove dead copper, pour order 5): 6651,5347 6453.17,5347 6242.82,5557.34 6242.82,7353.82 7103,8214 8100.45,8214 8320.6,7993.85 8320.6,7548.6 8311,7539 7585,7539 7309,7815 7095,7815 6499.76,7219.76 6499.76,5806.95 6669.86,5636.86 6669.86,5365.86
VSYS_5V on Inner2 (solid, remove dead copper, pour order 6): 7023,8589 7023,8825 7084,8886 7793,8886 7793,8589
VCC_MCU_3.3V on Top Layer (solid, remove dead copper, pour order 7): 7999,7392 7999,7429 8066,7496 8202.14,7496 8204.64,7493.5 8204.64,7391.79 7999.21,7391.79
VCC_MCU_3.3V on Inner2 (solid, remove dead copper, pour order 8): 5504,9427 9462,9427 9826,9063 9826,4163 4366,4163 4366,8289
GND on Top Layer (solid, remove dead copper, pour order 9): 4330,9169 10533,9169 11636,8066 11636,4444 10877,3685 4064,3685 3000,4749 3000,7839
GND on Inner1 (solid, remove dead copper, pour order 10): 5323,9911 10345,9911 10885,9371 10885,3704 10181,3000 7811,3000 5253,5558 5253,9841
GND on Bottom Layer (solid, remove dead copper, pour order 11): 4669,9561 10113,9561 11873,7801 11275,7203 11275,3906 4868,3906 4669,4105

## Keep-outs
Board Outline Layer:
  lines w10 net "": 6070,5104.1 ccw(c6188.11,5104.1) 6188.11,4985.99 8904.65,4985.99 ccw(c8904.65,5104.1) 9022.76,5104.1 9022.76,8804.89 ccw(c8904.65,8804.89) 8904.65,8923 6188.11,8923 ccw(c6188.11,8804.89) 6070,8804.89 6070,5104.1

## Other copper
Top Layer:
  region net VBAT: 6167.32,7521.93 6167.32,7720.46 6203.59,7720.46 6220.08,7703.97 6220.08,7639.92 6242,7618 6415,7618 6415,7522 6414.93,7521.93
  region net USB_VBUS: 6673.75,8011.84 6452.3,8011.84 6452.3,7926 6641,7926 6673.75,7958.75
  region net $4N2026: 8642,7804 8642,7880 8635,7887 8594,7887 8563,7918 8373,7918 8366,7911 8366,7825.54 8313,7772.54 8313,7662 8394,7662 8402,7670 8402,7720 8529,7847 8589,7847 8606,7830 8606,7804
  region net BGND: 6158,5516 6128,5516 6117,5527 6117,5662 6167,5712 6305,5712 6330,5737 6330,5980 6403,6053 6501.35,6053 6526.31,6028.03 6526.31,5309.31 6490,5273 6405.76,5273 6231.49,5447.27 6231.49,5587.9 6210.82,5608.57 6177,5608.57 6158,5589.57
Bottom Layer:
  region net VSYS_5V: 6549.08,5473.77 6549.08,5369.92 6565,5354 6671,5354 6671,5428.53 6625.76,5473.77

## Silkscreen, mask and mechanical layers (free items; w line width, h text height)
Mechanical Layer:
  lines w1 net "": 7211.73,4920.98 7881.02,4920.98 7881.02,5259.09 7211.73,5259.09 7211.73,4920.98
